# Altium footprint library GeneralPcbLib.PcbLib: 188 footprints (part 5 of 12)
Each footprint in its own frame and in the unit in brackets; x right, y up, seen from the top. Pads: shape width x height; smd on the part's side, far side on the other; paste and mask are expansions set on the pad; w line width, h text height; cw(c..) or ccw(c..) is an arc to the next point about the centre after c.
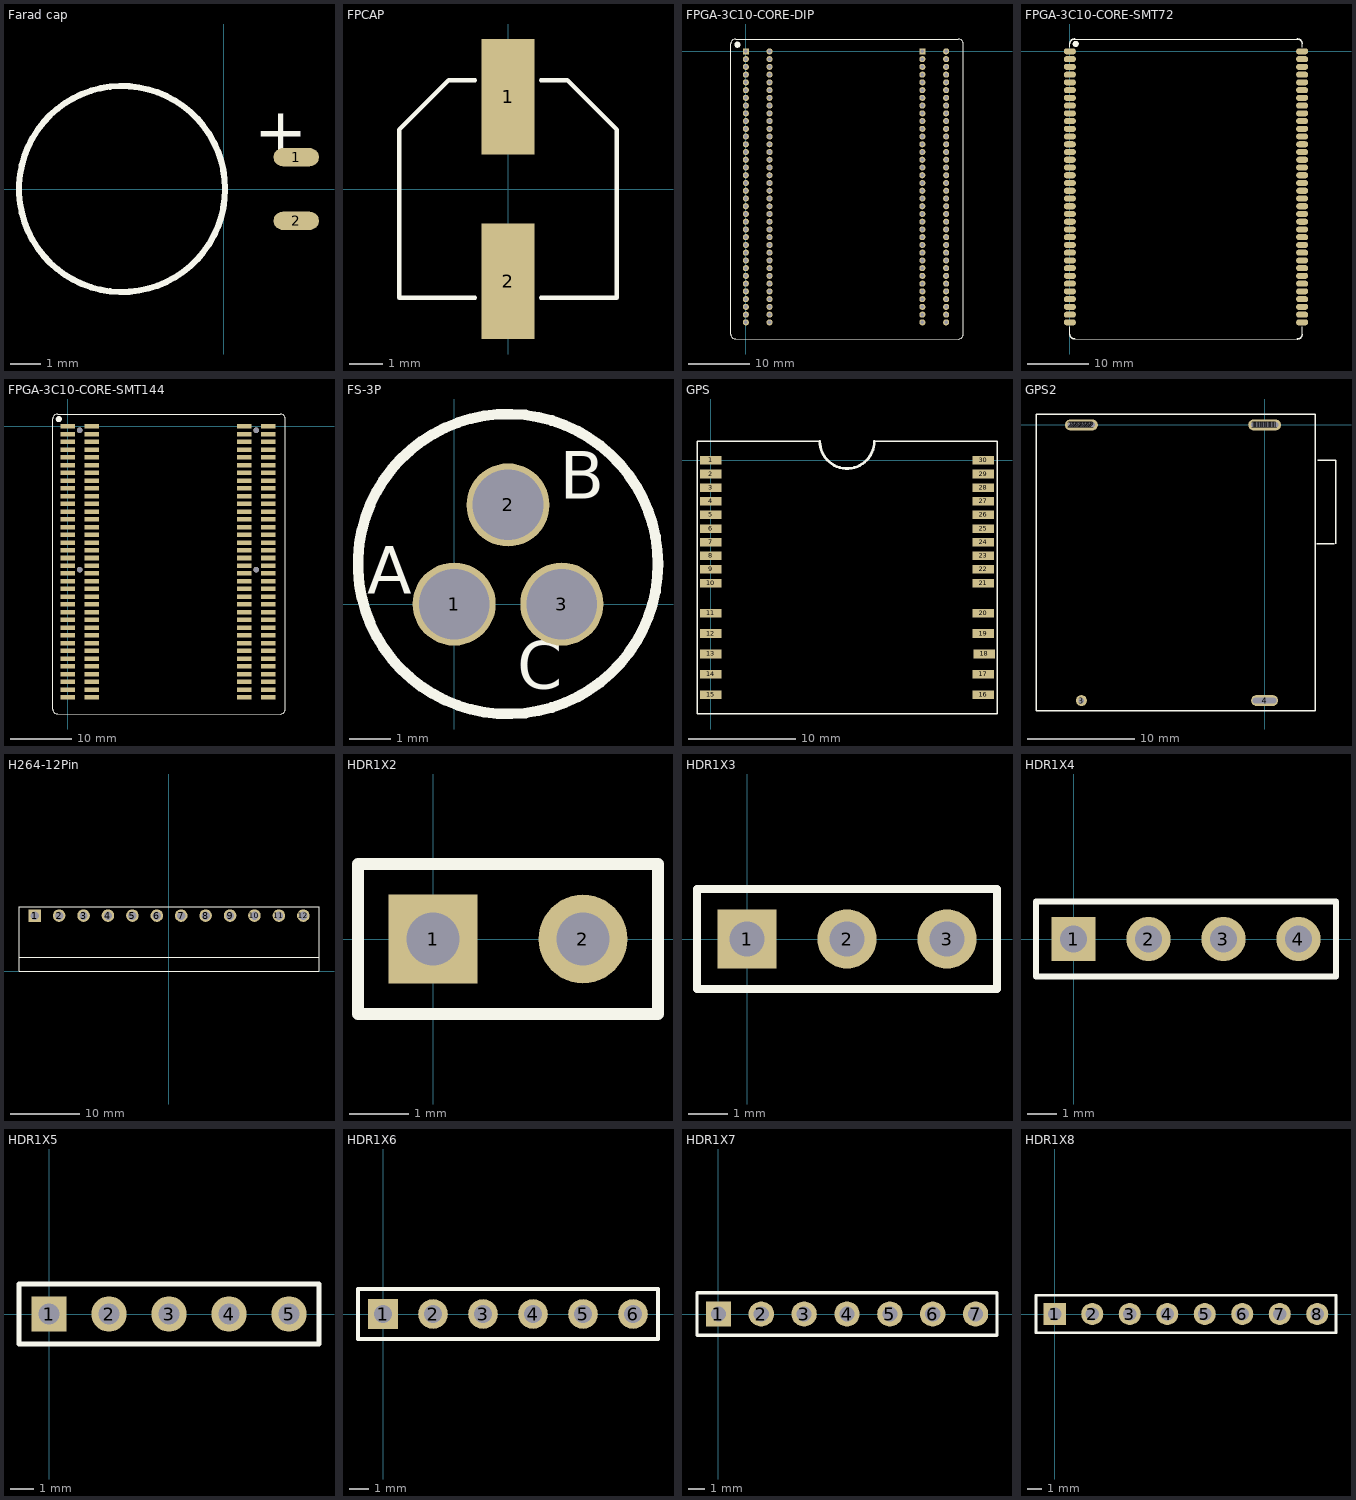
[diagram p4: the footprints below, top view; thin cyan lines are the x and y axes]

## Farad cap [mm]
pads (2):
  oval 1.5x0.6 smd: 1(2.4,1.05) 2(2.4,-1.05)
Top Overlay:
  circle w0.203: c-3.35,0 r3.4
  text "+" at 1.016,1.143 h1.52

## FPCAP [mm] "固态电容，220uF/6.3V"
pads (2):
  rect 1.6x3.5 smd: 1(0,2.8) 2(0,-2.8)
Top Overlay:
  lines w0.127: -1,-3.3 -3.3,-3.3 -3.3,1.8 -1.8,3.3 -1,3.3 ; 1,-3.3 3.3,-3.3 3.3,1.8 1.8,3.3 1,3.3

## FPGA-3C10-CORE-DIP [mm]
pads (144):
  rect 1x1 hole 0.6: 1(0,0) 144(28.956,0)
  round 1 hole 0.6: 2(0,-1.27) 3(0,-2.54) 4(0,-3.81) 5(0,-5.08) 6(0,-6.35) 7(0,-7.62) 8(0,-8.89) 9(0,-10.16) 10(0,-11.43) 11(0,-12.7) 12(0,-13.97) 13(0,-15.24) 14(0,-16.51) 15(0,-17.78) 16(0,-19.05) 17(0,-20.32) 18(0,-21.59) 19(0,-22.86) 20(0,-24.13) 21(0,-25.4) 22(0,-26.67) 23(0,-27.94) 24(0,-29.21) 25(0,-30.48) 26(0,-31.75) 27(0,-33.02) 28(0,-34.29) 29(0,-35.56) 30(0,-36.83) 31(0,-38.1) 32(0,-39.37) 33(0,-40.64) 34(0,-41.91) 35(0,-43.18) 36(0,-44.45) 37(32.856,-44.45) 38(32.856,-43.18) 39(32.856,-41.91) 40(32.856,-40.64) 41(32.856,-39.37) 42(32.856,-38.1) 43(32.856,-36.83) 44(32.856,-35.56) 45(32.856,-34.29) 46(32.856,-33.02) 47(32.856,-31.75) 48(32.856,-30.48) 49(32.856,-29.21) 50(32.856,-27.94) 51(32.856,-26.67) 52(32.856,-25.4) 53(32.856,-24.13) 54(32.856,-22.86) 55(32.856,-21.59) 56(32.856,-20.32) 57(32.856,-19.05) 58(32.856,-17.78) 59(32.856,-16.51) 60(32.856,-15.24) 61(32.856,-13.97) 62(32.856,-12.7) 63(32.856,-11.43) 64(32.856,-10.16) 65(32.856,-8.89) 66(32.856,-7.62) 67(32.856,-6.35) 68(32.856,-5.08) 69(32.856,-3.81) 70(32.856,-2.54) 71(32.856,-1.27) 72(32.856,0) 73(3.9,0) 74(3.9,-1.27) 75(3.9,-2.54) 76(3.9,-3.81) 77(3.9,-5.08) 78(3.9,-6.35) 79(3.9,-7.62) 80(3.9,-8.89) 81(3.9,-10.16) 82(3.9,-11.43) 83(3.9,-12.7) 84(3.9,-13.97) 85(3.9,-15.24) 86(3.9,-16.51) 87(3.9,-17.78) 88(3.9,-19.05) 89(3.9,-20.32) 90(3.9,-21.59) 91(3.9,-22.86) 92(3.9,-24.13) 93(3.9,-25.4) 94(3.9,-26.67) 95(3.9,-27.94) 96(3.9,-29.21) 97(3.9,-30.48) 98(3.9,-31.75) 99(3.9,-33.02) 100(3.9,-34.29) 101(3.9,-35.56) 102(3.9,-36.83) 103(3.9,-38.1) 104(3.9,-39.37) 105(3.9,-40.64) 106(3.9,-41.91) 107(3.9,-43.18) 108(3.9,-44.45) 109(28.956,-44.45) 110(28.956,-43.18) 111(28.956,-41.91) 112(28.956,-40.64) 113(28.956,-39.37) 114(28.956,-38.1) 115(28.956,-36.83) 116(28.956,-35.56) 117(28.956,-34.29) 118(28.956,-33.02) 119(28.956,-31.75) 120(28.956,-30.48) 121(28.956,-29.21) 122(28.956,-27.94) 123(28.956,-26.67) 124(28.956,-25.4) 125(28.956,-24.13) 126(28.956,-22.86) 127(28.956,-21.59) 128(28.956,-20.32) 129(28.956,-19.05) 130(28.956,-17.78) 131(28.956,-16.51) 132(28.956,-15.24) 133(28.956,-13.97) 134(28.956,-12.7) 135(28.956,-11.43) 136(28.956,-10.16) 137(28.956,-8.89) 138(28.956,-7.62) 139(28.956,-6.35) 140(28.956,-5.08) 141(28.956,-3.81) 142(28.956,-2.54) 143(28.956,-1.27)
Top Overlay:
  circle w0.508: c-1.375,1.1 r0.254
  lines w0.127: -2.45,-46.408 ccw(c-1.688,-46.408) -1.688,-47.17 34.888,-47.178 ccw(c34.888,-46.416) 35.65,-46.416 35.65,1.269 ccw(c34.888,1.269) 34.888,2.031 -1.688,2.031 ccw(c-1.688,1.269) -2.45,1.269 -2.45,-46.408

## FPGA-3C10-CORE-SMT72 [mm]
height 6
pads (72):
  oval 2x1 smd: 1(0,0) 2(0,-1.27) 3(0,-2.54) 4(0,-3.81) 5(0,-5.08) 6(0,-6.35) 7(0,-7.62) 8(0,-8.89) 9(0,-10.16) 10(0,-11.43) 11(0,-12.7) 12(0,-13.97) 13(0,-15.24) 14(0,-16.51) 15(0,-17.78) 16(0,-19.05) 17(0,-20.32) 18(0,-21.59) 19(0,-22.86) 20(0,-24.13) 21(0,-25.4) 22(0,-26.67) 23(0,-27.94) 24(0,-29.21) 25(0,-30.48) 26(0,-31.75) 27(0,-33.02) 28(0,-34.29) 29(0,-35.56) 30(0,-36.83) 31(0,-38.1) 32(0,-39.37) 33(0,-40.64) 34(0,-41.91) 35(0,-43.18) 36(0,-44.45) 37(38.1,-44.45) 38(38.1,-43.18) 39(38.1,-41.91) 40(38.1,-40.64) 41(38.1,-39.37) 42(38.1,-38.1) 43(38.1,-36.83) 44(38.1,-35.56) 45(38.1,-34.29) 46(38.1,-33.02) 47(38.1,-31.75) 48(38.1,-30.48) 49(38.1,-29.21) 50(38.1,-27.94) 51(38.1,-26.67) 52(38.1,-25.4) 53(38.1,-24.13) 54(38.1,-22.86) 55(38.1,-21.59) 56(38.1,-20.32) 57(38.1,-19.05) 58(38.1,-17.78) 59(38.1,-16.51) 60(38.1,-15.24) 61(38.1,-13.97) 62(38.1,-12.7) 63(38.1,-11.43) 64(38.1,-10.16) 65(38.1,-8.89) 66(38.1,-7.62) 67(38.1,-6.35) 68(38.1,-5.08) 69(38.1,-3.81) 70(38.1,-2.54) 71(38.1,-1.27) 72(38.1,0)
Top Overlay:
  circle w0.508: c0.959,1.221 r0.254
  lines w0.127: 0,-46.408 0,-45.2 ; 0,0.7 0,1.269 ; 0.762,-47.17 37.338,-47.178 ; 0.762,2.031 37.338,2.031 ; 38.1,-46.416 38.1,-45.2 ; 38.1,0.7 38.1,1.269 ; 38.1,-45.2 38.1,-45.2
  lines w0.254: 0,-46.408 ccw(c0.762,-46.408) 0.762,-47.17 ; 0,1.269 cw(c0.762,1.269) 0.762,2.031 ; 37.338,-47.178 ccw(c37.338,-46.416) 38.1,-46.416 ; 37.338,2.031 cw(c37.338,1.269) 38.1,1.269

## FPGA-3C10-CORE-SMT144 [mm]
pads (148):
  round 0.9 hole 0.9: 0(1.95,-23.495) 0(1.95,-0.635) 0(30.906,-23.495) 0(30.906,-0.635)
  rect 2.4x0.74 smd: 1(0,0) 2(0,-1.27) 3(0,-2.54) 4(0,-3.81) 5(0,-5.08) 6(0,-6.35) 7(0,-7.62) 8(0,-8.89) 9(0,-10.16) 10(0,-11.43) 11(0,-12.7) 12(0,-13.97) 13(0,-15.24) 14(0,-16.51) 15(0,-17.78) 16(0,-19.05) 17(0,-20.32) 18(0,-21.59) 19(0,-22.86) 20(0,-24.13) 21(0,-25.4) 22(0,-26.67) 23(0,-27.94) 24(0,-29.21) 25(0,-30.48) 26(0,-31.75) 27(0,-33.02) 28(0,-34.29) 29(0,-35.56) 30(0,-36.83) 31(0,-38.1) 32(0,-39.37) 33(0,-40.64) 34(0,-41.91) 35(0,-43.18) 36(0,-44.45) 37(32.856,-44.45) 38(32.856,-43.18) 39(32.856,-41.91) 40(32.856,-40.64) 41(32.856,-39.37) 42(32.856,-38.1) 43(32.856,-36.83) 44(32.856,-35.56) 45(32.856,-34.29) 46(32.856,-33.02) 47(32.856,-31.75) 48(32.856,-30.48) 49(32.856,-29.21) 50(32.856,-27.94) 51(32.856,-26.67) 52(32.856,-25.4) 53(32.856,-24.13) 54(32.856,-22.86) 55(32.856,-21.59) 56(32.856,-20.32) 57(32.856,-19.05) 58(32.856,-17.78) 59(32.856,-16.51) 60(32.856,-15.24) 61(32.856,-13.97) 62(32.856,-12.7) 63(32.856,-11.43) 64(32.856,-10.16) 65(32.856,-8.89) 66(32.856,-7.62) 67(32.856,-6.35) 68(32.856,-5.08) 69(32.856,-3.81) 70(32.856,-2.54) 71(32.856,-1.27) 72(32.856,0) 73(3.9,0) 74(3.9,-1.27) 75(3.9,-2.54) 76(3.9,-3.81) 77(3.9,-5.08) 78(3.9,-6.35) 79(3.9,-7.62) 80(3.9,-8.89) 81(3.9,-10.16) 82(3.9,-11.43) 83(3.9,-12.7) 84(3.9,-13.97) 85(3.9,-15.24) 86(3.9,-16.51) 87(3.9,-17.78) 88(3.9,-19.05) 89(3.9,-20.32) 90(3.9,-21.59) 91(3.9,-22.86) 92(3.9,-24.13) 93(3.9,-25.4) 94(3.9,-26.67) 95(3.9,-27.94) 96(3.9,-29.21) 97(3.9,-30.48) 98(3.9,-31.75) 99(3.9,-33.02) 100(3.9,-34.29) 101(3.9,-35.56) 102(3.9,-36.83) 103(3.9,-38.1) 104(3.9,-39.37) 105(3.9,-40.64) 106(3.9,-41.91) 107(3.9,-43.18) 108(3.9,-44.45) 109(28.956,-44.45) 110(28.956,-43.18) 111(28.956,-41.91) 112(28.956,-40.64) 113(28.956,-39.37) 114(28.956,-38.1) 115(28.956,-36.83) 116(28.956,-35.56) 117(28.956,-34.29) 118(28.956,-33.02) 119(28.956,-31.75) 120(28.956,-30.48) 121(28.956,-29.21) 122(28.956,-27.94) 123(28.956,-26.67) 124(28.956,-25.4) 125(28.956,-24.13) 126(28.956,-22.86) 127(28.956,-21.59) 128(28.956,-20.32) 129(28.956,-19.05) 130(28.956,-17.78) 131(28.956,-16.51) 132(28.956,-15.24) 133(28.956,-13.97) 134(28.956,-12.7) 135(28.956,-11.43) 136(28.956,-10.16) 137(28.956,-8.89) 138(28.956,-7.62) 139(28.956,-6.35) 140(28.956,-5.08) 141(28.956,-3.81) 142(28.956,-2.54) 143(28.956,-1.27) 144(28.956,0)
Top Overlay:
  circle w0.508: c-1.475,1.2 r0.254
  lines w0.102: -2.45,-46.408 ccw(c-1.688,-46.408) -1.688,-47.17 ; -2.45,1.269 cw(c-1.688,1.269) -1.688,2.031 ; 34.888,-47.178 ccw(c34.888,-46.416) 35.65,-46.416 ; 34.888,2.031 cw(c34.888,1.269) 35.65,1.269
  lines w0.127: -2.45,-46.408 -2.45,1.269 ; -1.688,-47.17 34.888,-47.178 ; -1.688,2.031 34.888,2.031 ; 35.65,-46.416 35.65,1.269

## FS-3P [mm] "三芯防水插座"
pads (3):
  round 2 hole 1.7: 1(0,0) 2(1.295,2.388) 3(2.591,0)
Top Overlay:
  circle w0.254: c1.295,0.965 r3.61
  text "A" at -1.016,0.254 h1.14
  text "B" at 2.54,2.54 h1.14
  text "C" at 1.524,-2.032 h1.14

## GPS [mm] "ET-314"
pads (30):
  rect 2x0.8 smd: 1(0,0) 2(0,-1.27) 3(0,-2.54) 4(0,-3.81) 5(0,-5.08) 6(0,-6.35) 7(0,-7.62) 8(0,-8.89) 9(0,-10.16) 10(0,-11.43) 11(0,-14.224) 12(0,-16.129) 13(0,-18.034) 14(0,-19.939) 15(0,-21.844) 16(25.4,-21.844) 17(25.4,-19.939) 18(25.476,-18.034) 19(25.4,-16.129) 20(25.4,-14.224) 21(25.4,-11.43) 22(25.4,-10.16) 23(25.4,-8.89) 24(25.4,-7.62) 25(25.4,-6.35) 26(25.4,-5.08) 27(25.4,-3.81) 28(25.4,-2.54) 29(25.4,-1.27) 30(25.4,0)
Top Overlay:
  lines w0.127: 10.16,1.778 -1.28,1.778 -1.28,-23.622 26.67,-23.622 26.67,1.778 15.24,1.778
  lines w0.254: 10.16,1.778 ccw(c12.7,1.778) 15.24,1.778

## GPS2 [mil]
pads (36):
  round 40 hole 20: 1(-40,0) 1(-35,0) 1(-30,0) 1(-25,0) 1(-20,0) 1(-15,0) 1(-10,0) 1(-5,0) 1(0,0) 1(5,0) 1(10,0) 1(15,0) 1(20,0) 1(25,0) 1(30,0) 1(35,0) 1(40,0) 2(-710,0) 2(-705,0) 2(-700,0) 2(-695,0) 2(-690,0) 2(-685,0) 2(-680,0) 2(-675,0) 2(-670,0) 2(-665,0) 2(-660,0) 2(-655,0) 2(-650,0) 2(-645,0) 2(-640,0) 2(-635,0) 2(-630,0) 3(-670,-1007.87)
  oval 98.43x39.37 hole 19.68 slot 86.61 at 0.1 deg: 4(0,-1007.87)
Top Overlay:
  lines w5: 190,-435 255,-435 ; 195,-130 260,-130 260,-435 ; -835,-1045 70,-1045 185,-1045 185,40 -835,40 -835,-1045

## H264-12Pin [mm]
pads (12):
  rect 1.8x1.8 hole 1.2: 1(-19.25,8)
  round 1.8 hole 1.2: 2(-15.75,8) 3(-12.25,8) 4(-8.75,8) 5(-5.25,8) 6(-1.75,8) 7(1.75,8) 8(5.25,8) 9(8.75,8) 10(12.25,8) 11(15.75,8) 12(19.25,8)
Top Overlay:
  lines w0.127: -21.5,2.023 21.5,2.023 ; -21.5,0 -21.5,9.3 21.5,9.3 21.5,0 -21.5,0

## HDR1X2 [mm] "Connector; Header; 2 Position"
pads (2):
  rect 1.5x1.5 hole 0.9: 1(0,0)
  round 1.5 hole 0.9: 2(2.54,0)
Top Overlay:
  lines w0.2: -1.27,-1.27 3.81,-1.27 3.81,1.27 -1.27,1.27 -1.27,-1.27
3D body: height 7.58, standoff -2.94, extent -1.27,-1.27 1.27,1.27
3D body: height 7.58, standoff -2.94, extent 1.27,-1.27 3.81,1.27

## HDR1X3 [mm] "Connector; Header; 3 Position"
pads (3):
  rect 1.5x1.5 hole 0.9: 1(0,0)
  round 1.5 hole 0.9: 2(2.54,0) 3(5.08,0)
Top Overlay:
  lines w0.2: -1.27,-1.27 -1.27,1.27 6.35,1.27 6.35,-1.27 -1.27,-1.27
3D body: height 7.58, standoff -2.94, extent -1.27,-1.27 1.27,1.27
3D body: height 7.58, standoff -2.94, extent 1.27,-1.27 3.81,1.27
3D body: height 7.58, standoff -2.94, extent 3.81,-1.27 6.35,1.27

## HDR1X4 [mm] "Connector; Header; 4 Position"
pads (4):
  rect 1.5x1.5 hole 0.9: 1(0,0)
  round 1.5 hole 0.9: 2(2.54,0) 3(5.08,0) 4(7.62,0)
Top Overlay:
  lines w0.2: -1.27,-1.27 -1.27,1.27 8.89,1.27 8.89,-1.27 -1.27,-1.27
3D body: height 7.58, standoff -2.94, extent -1.27,-1.27 1.27,1.27
3D body: height 7.58, standoff -2.94, extent 1.27,-1.27 3.81,1.27
3D body: height 7.58, standoff -2.94, extent 3.81,-1.27 6.35,1.27
3D body: height 7.58, standoff -2.94, extent 6.35,-1.27 8.89,1.27

## HDR1X5 [mm] "Connector; Header; 5 Position"
pads (5):
  rect 1.5x1.5 hole 0.9: 1(0,0)
  round 1.5 hole 0.9: 2(2.54,0) 3(5.08,0) 4(7.62,0) 5(10.16,0)
Top Overlay:
  lines w0.2: -1.27,-1.27 -1.27,1.27 11.43,1.27 11.43,-1.27 -1.27,-1.27
3D body: height 7.58, standoff -2.94, extent -1.27,-1.27 1.27,1.27
3D body: height 7.58, standoff -2.94, extent 1.27,-1.27 3.81,1.27
3D body: height 7.58, standoff -2.94, extent 3.81,-1.27 6.35,1.27
3D body: height 7.58, standoff -2.94, extent 6.35,-1.27 8.89,1.27
3D body: height 7.58, standoff -2.94, extent 8.89,-1.27 11.43,1.27

## HDR1X6 [mm] "Connector; Header; 6 Position"
pads (6):
  rect 1.5x1.5 hole 0.9: 1(0,0)
  round 1.5 hole 0.9: 2(2.54,0) 3(5.08,0) 4(7.62,0) 5(10.16,0) 6(12.7,0)
Top Overlay:
  lines w0.2: -1.27,-1.27 13.97,-1.27 13.97,1.27 -1.27,1.27 -1.27,-1.27
3D body: height 7.58, standoff -2.94, extent -1.27,-1.27 1.27,1.27
3D body: height 7.58, standoff -2.94, extent 1.27,-1.27 3.81,1.27
3D body: height 7.58, standoff -2.94, extent 3.81,-1.27 6.35,1.27
3D body: height 7.58, standoff -2.94, extent 6.35,-1.27 8.89,1.27
3D body: height 7.58, standoff -2.94, extent 8.89,-1.27 11.43,1.27
3D body: height 7.58, standoff -2.94, extent 11.43,-1.27 13.97,1.27

## HDR1X7 [mm] "Connector; Header; 7 Position"
pads (7):
  rect 1.5x1.5 hole 0.9: 1(0,0)
  round 1.5 hole 0.9: 2(2.54,0) 3(5.08,0) 4(7.62,0) 5(10.16,0) 6(12.7,0) 7(15.24,0)
Top Overlay:
  lines w0.2: -1.27,-1.27 16.51,-1.27 16.51,1.27 -1.27,1.27 -1.27,-1.27
3D body: height 7.58, standoff -2.94, extent -1.27,-1.27 1.27,1.27
3D body: height 7.58, standoff -2.94, extent 1.27,-1.27 3.81,1.27
3D body: height 7.58, standoff -2.94, extent 3.81,-1.27 6.35,1.27
3D body: height 7.58, standoff -2.94, extent 6.35,-1.27 8.89,1.27
3D body: height 7.58, standoff -2.94, extent 8.89,-1.27 11.43,1.27
3D body: height 7.58, standoff -2.94, extent 11.43,-1.27 13.97,1.27
3D body: height 7.58, standoff -2.94, extent 13.97,-1.27 16.51,1.27

## HDR1X8 [mm] "Connector; Header; 8 Position"
pads (8):
  rect 1.5x1.5 hole 0.9: 1(0,0)
  round 1.5 hole 0.9: 2(2.54,0) 3(5.08,0) 4(7.62,0) 5(10.16,0) 6(12.7,0) 7(15.24,0) 8(17.78,0)
Top Overlay:
  lines w0.2: -1.27,-1.27 19.05,-1.27 19.05,1.27 -1.27,1.27 -1.27,-1.27
3D body: height 7.58, standoff -2.94, extent -1.27,-1.27 1.27,1.27
3D body: height 7.58, standoff -2.94, extent 1.27,-1.27 3.81,1.27
3D body: height 7.58, standoff -2.94, extent 3.81,-1.27 6.35,1.27
3D body: height 7.58, standoff -2.94, extent 6.35,-1.27 8.89,1.27
3D body: height 7.58, standoff -2.94, extent 8.89,-1.27 11.43,1.27
3D body: height 7.58, standoff -2.94, extent 11.43,-1.27 13.97,1.27
3D body: height 7.58, standoff -2.94, extent 13.97,-1.27 16.51,1.27
3D body: height 7.58, standoff -2.94, extent 16.51,-1.27 19.05,1.27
